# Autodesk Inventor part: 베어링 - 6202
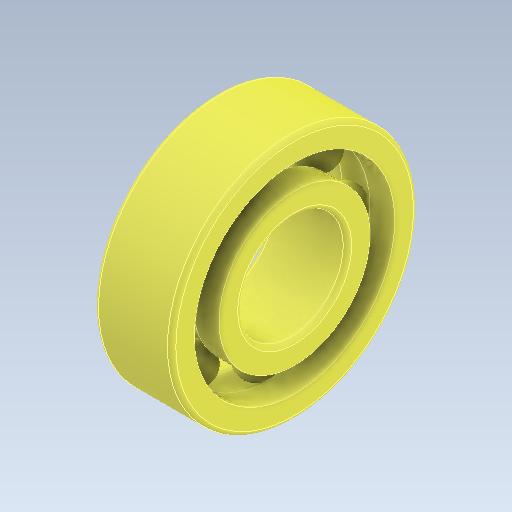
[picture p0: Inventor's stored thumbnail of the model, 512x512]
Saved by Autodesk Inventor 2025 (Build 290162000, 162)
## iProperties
Created: 2024-07
Part Number: 베어링 - 6202
Material: 강, 연강
Description: 깊은 그루브 볼 베어링
Document SubType Name: Modeling
Designer: 미서니
Density: 7.86 g/cm^3
Appearance: 기본값
Author: jhkim
Sending System: Autodesk Inventor 2025
Preprocessor: ST-DEVELOPER v20
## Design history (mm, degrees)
feature "Solid1"
feature "Solid1:1"
feature "Solid1:2"
feature "Solid1:3"
feature "Solid1:4"
feature "Solid1:5"
feature "Solid1:6"
feature "Solid1:7"
feature "Solid1:8"
feature "Solid1:9"
node "솔리드1"
node "솔리드2"
node "솔리드3"
node "솔리드4"
node "솔리드5"
node "솔리드6"
node "솔리드7"
node "솔리드8"
node "솔리드9"
node "솔리드10"
